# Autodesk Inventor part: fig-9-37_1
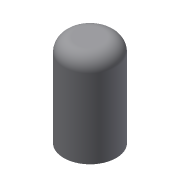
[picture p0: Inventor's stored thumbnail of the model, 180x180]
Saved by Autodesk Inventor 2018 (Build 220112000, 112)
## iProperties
Created: 2013-03
Part Number: fig-9-37_1
Material: Generic
Document SubType Name: Modeling
Designer: CADCIM
Density: 1 g/cm^3
Appearance: Default
Author: CADCIM
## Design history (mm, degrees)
sketch "Sketch1"
  geometry: C1 r 10 at (0, 0); 1 further point
  constraints: 1 centre point, 1 coincident
  dimensions: "d0" = 20 diameter of C1
extrude "Extrusion1" new body sketch "Sketch1" distance "d2" = 35; taper "d3" = 0 deg
fillet "Fillet1" dims "d4" = 5
shell "Shell1" dims "d5" = 2
body "Solid1"
